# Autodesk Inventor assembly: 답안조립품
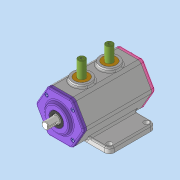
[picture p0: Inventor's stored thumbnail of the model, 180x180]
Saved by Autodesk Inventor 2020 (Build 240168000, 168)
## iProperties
Created: 2021-06
Part Number: 답안조립품
Document SubType Name: Assembly
Designer: PC2-03
Author: PC2-03
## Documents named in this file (11)
- C:\Users\PC2-03\Desktop\710606V1018\답안조립품.iam
- C:\Users\PC2-03\Desktop\710606V1018\본체.ipt
- C:\Users\PC2-03\Desktop\710606V1018\뒷커버.ipt
- C:\Users\PC2-03\Desktop\710606V1018\베어링 6302.ipt
- C:\Users\PC2-03\Desktop\710606V1018\편심축.ipt
- C:\Users\PC2-03\Desktop\710606V1018\부시.ipt
- C:\Users\PC2-03\Desktop\710606V1018\슬라이더.ipt
- C:\Users\PC2-03\Desktop\710606V1018\베어링 6203.ipt
- C:\Users\PC2-03\Desktop\710606V1018\앞커버.ipt
- C:\Users\PC2-03\Desktop\710606V1018\오일실.ipt
- C:\Users\PC2-03\Desktop\710606V1018\볼트 M4.ipt
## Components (10 placed, 3 different names)
1. 7-베어링 6203:1
2. 8-오일실:1 — 플러쉬:3
3. 9-M4-소켓머리:1
4. 9-M4-소켓머리:3
5. 9-M4-소켓머리:4
6. 9-M4-소켓머리:5
7. 9-M4-소켓머리:2
8. 9-M4-소켓머리:6
9. 9-M4-소켓머리:7
10. 9-M4-소켓머리:8
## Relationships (1: Flush 1)
- 플러쉬:3 [Flush]: 8-오일실:1
